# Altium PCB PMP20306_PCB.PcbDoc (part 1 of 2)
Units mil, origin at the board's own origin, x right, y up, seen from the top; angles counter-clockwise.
Board outline 1000 x 1500 mil, 4 copper layers (Top Layer, Signal Layer 1, Signal Layer 2, Bottom Layer), stack 42.6 mil thick; 50 components, 30 nets, 132 pads, 42 vias.
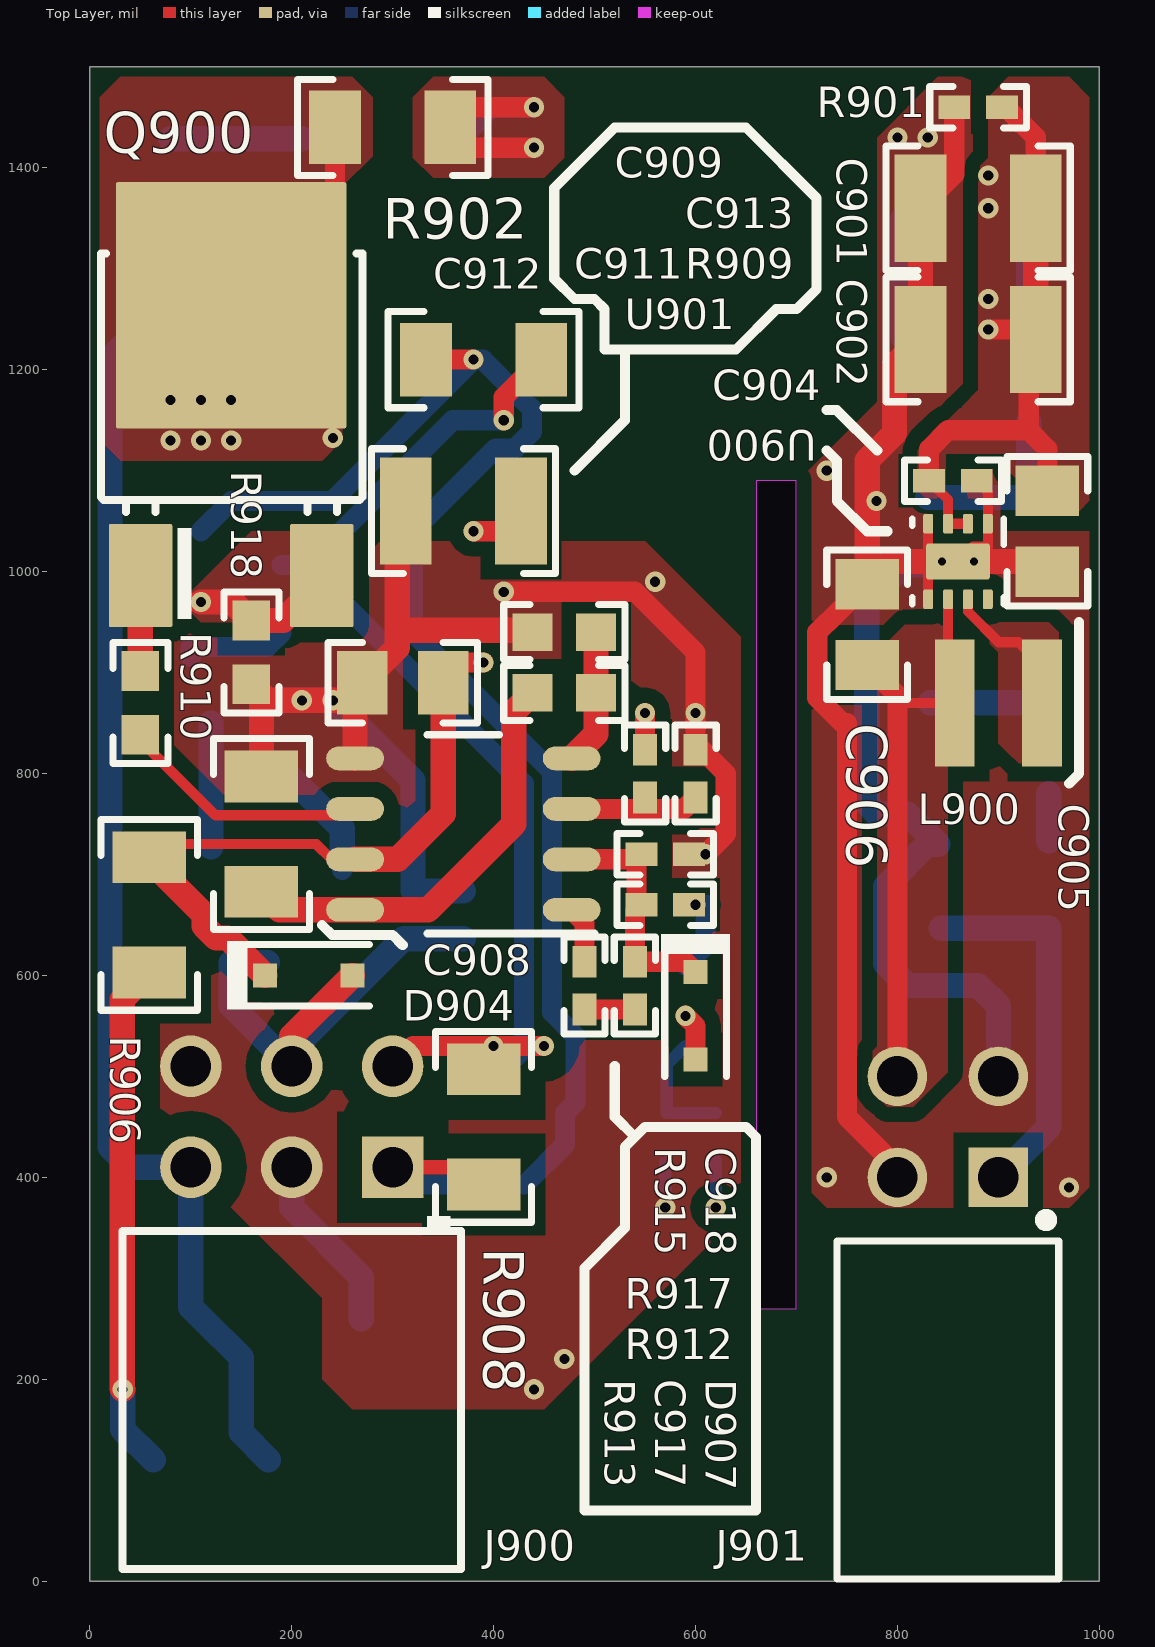
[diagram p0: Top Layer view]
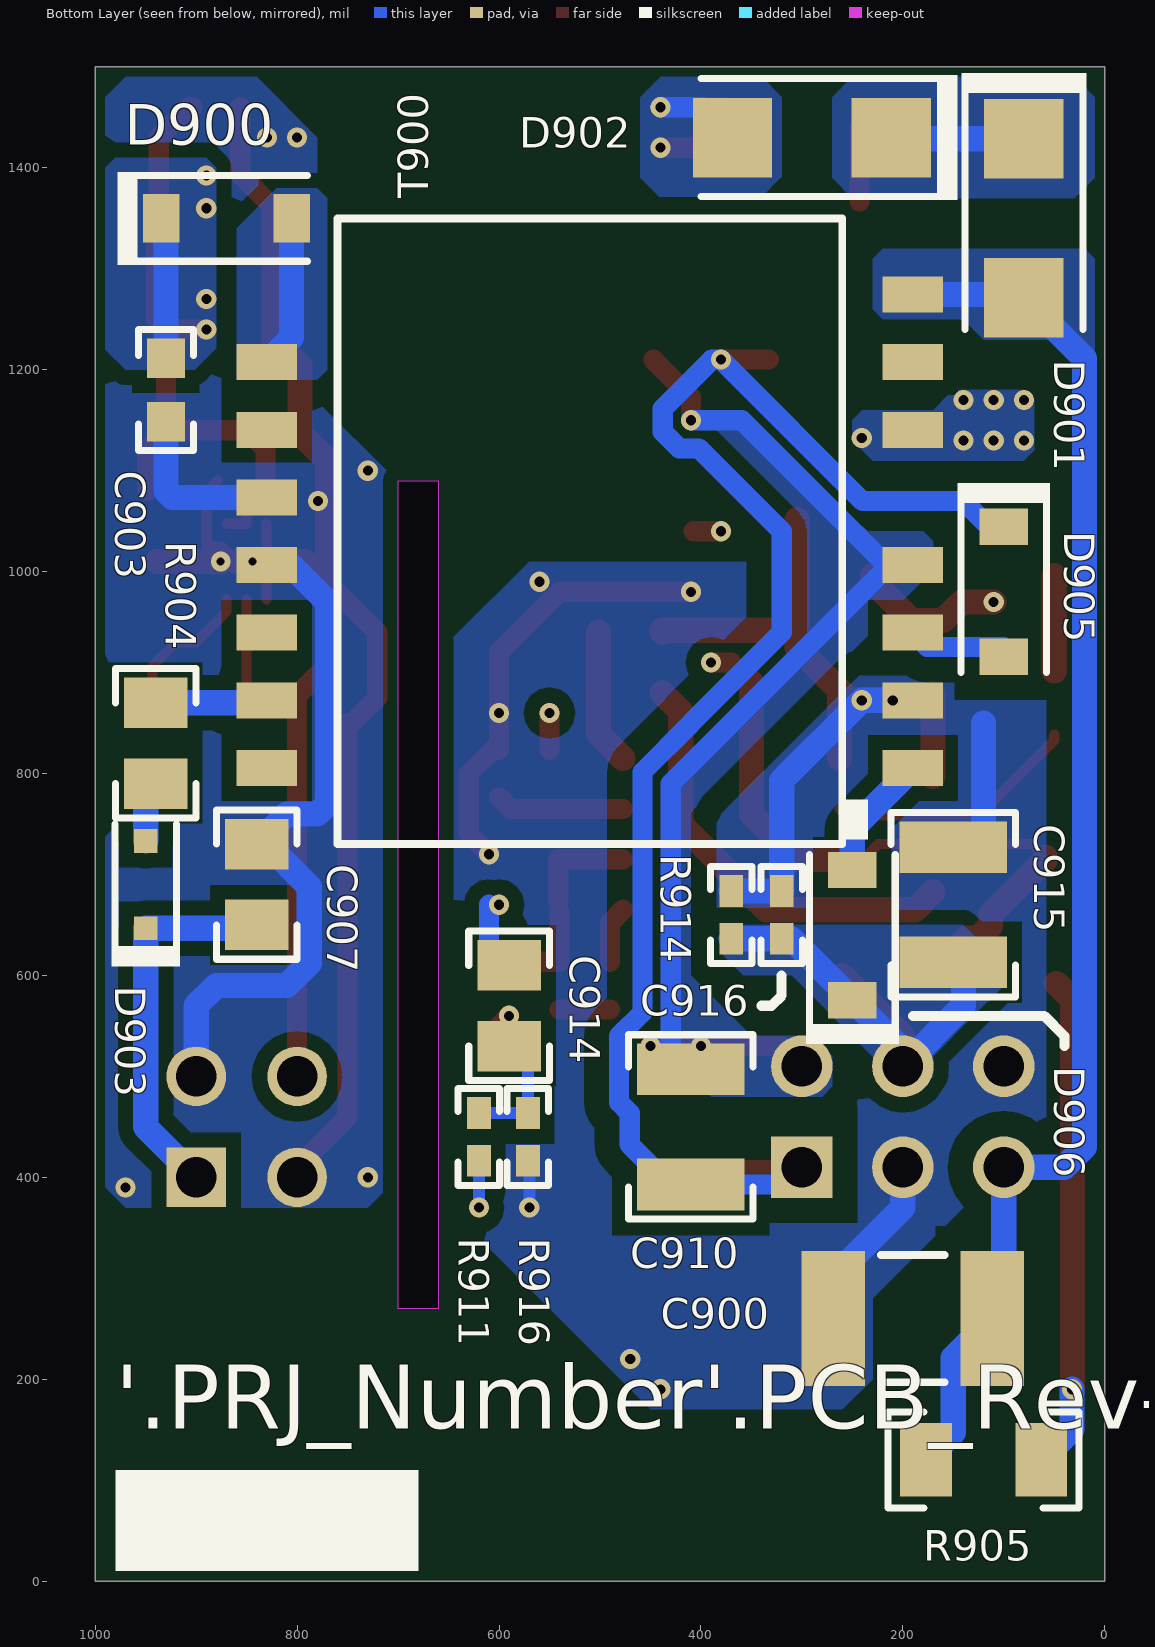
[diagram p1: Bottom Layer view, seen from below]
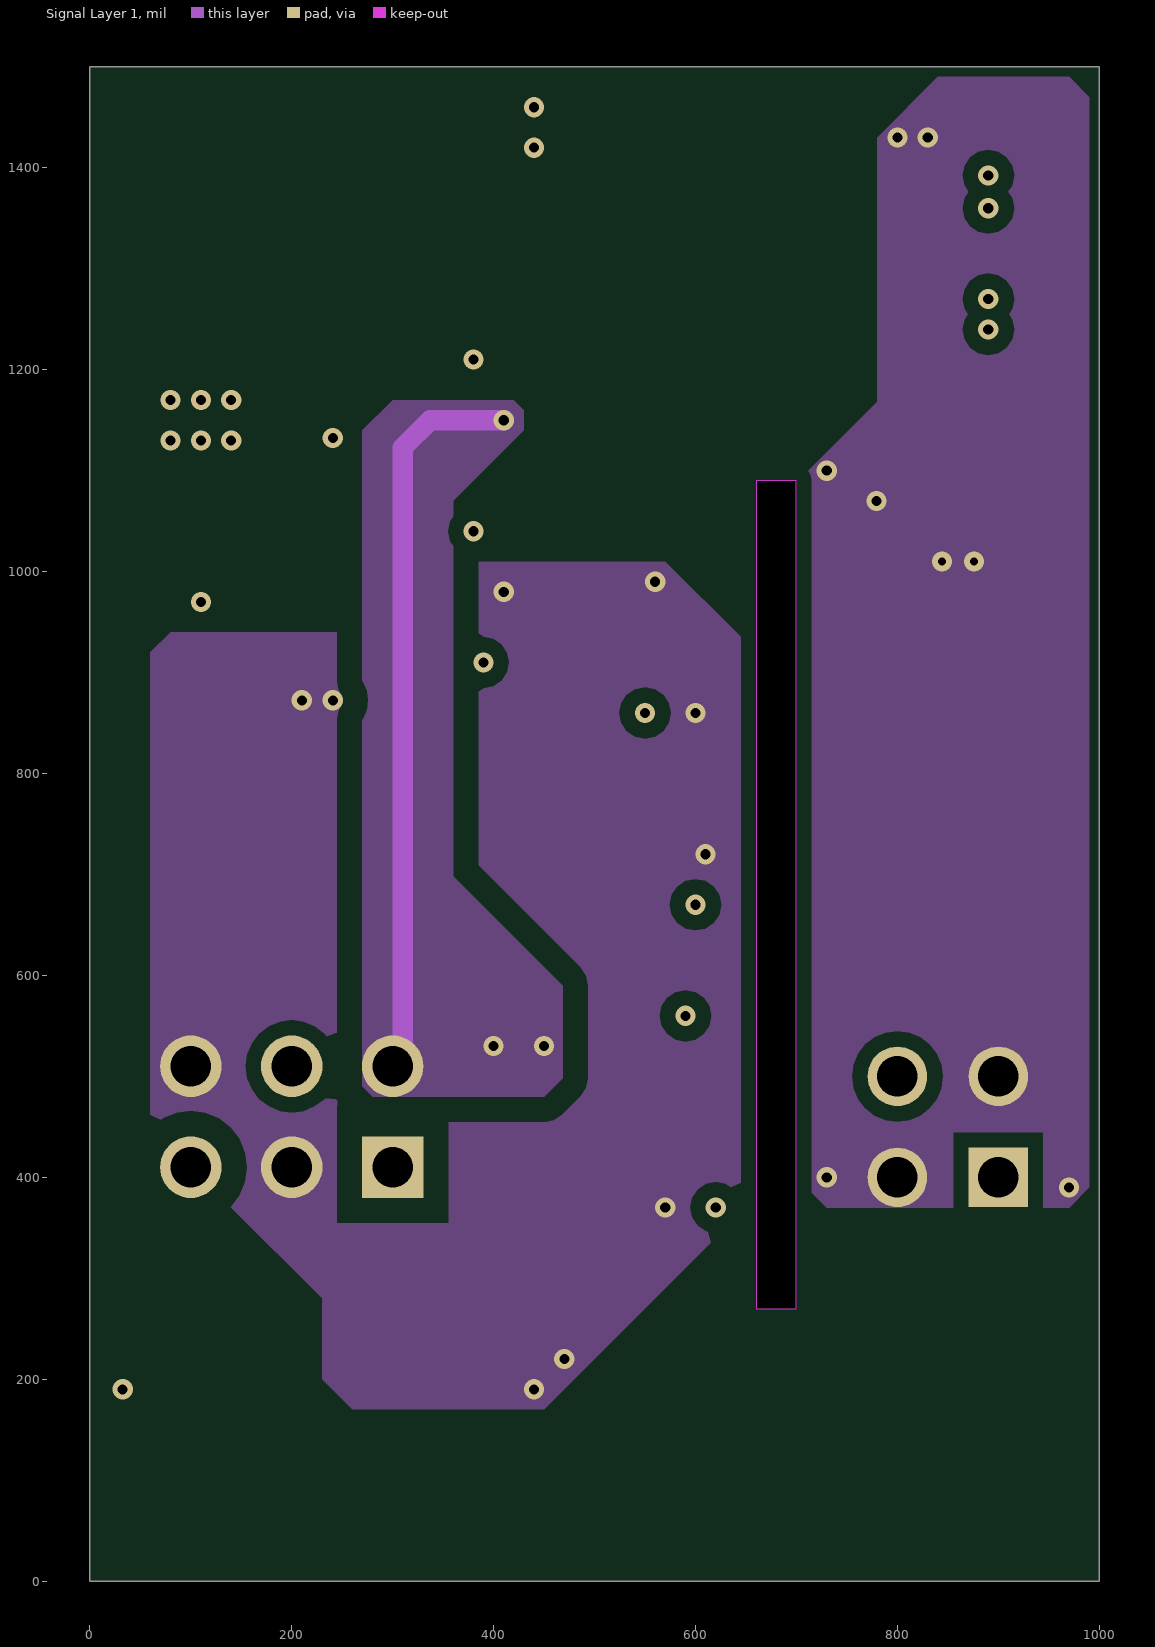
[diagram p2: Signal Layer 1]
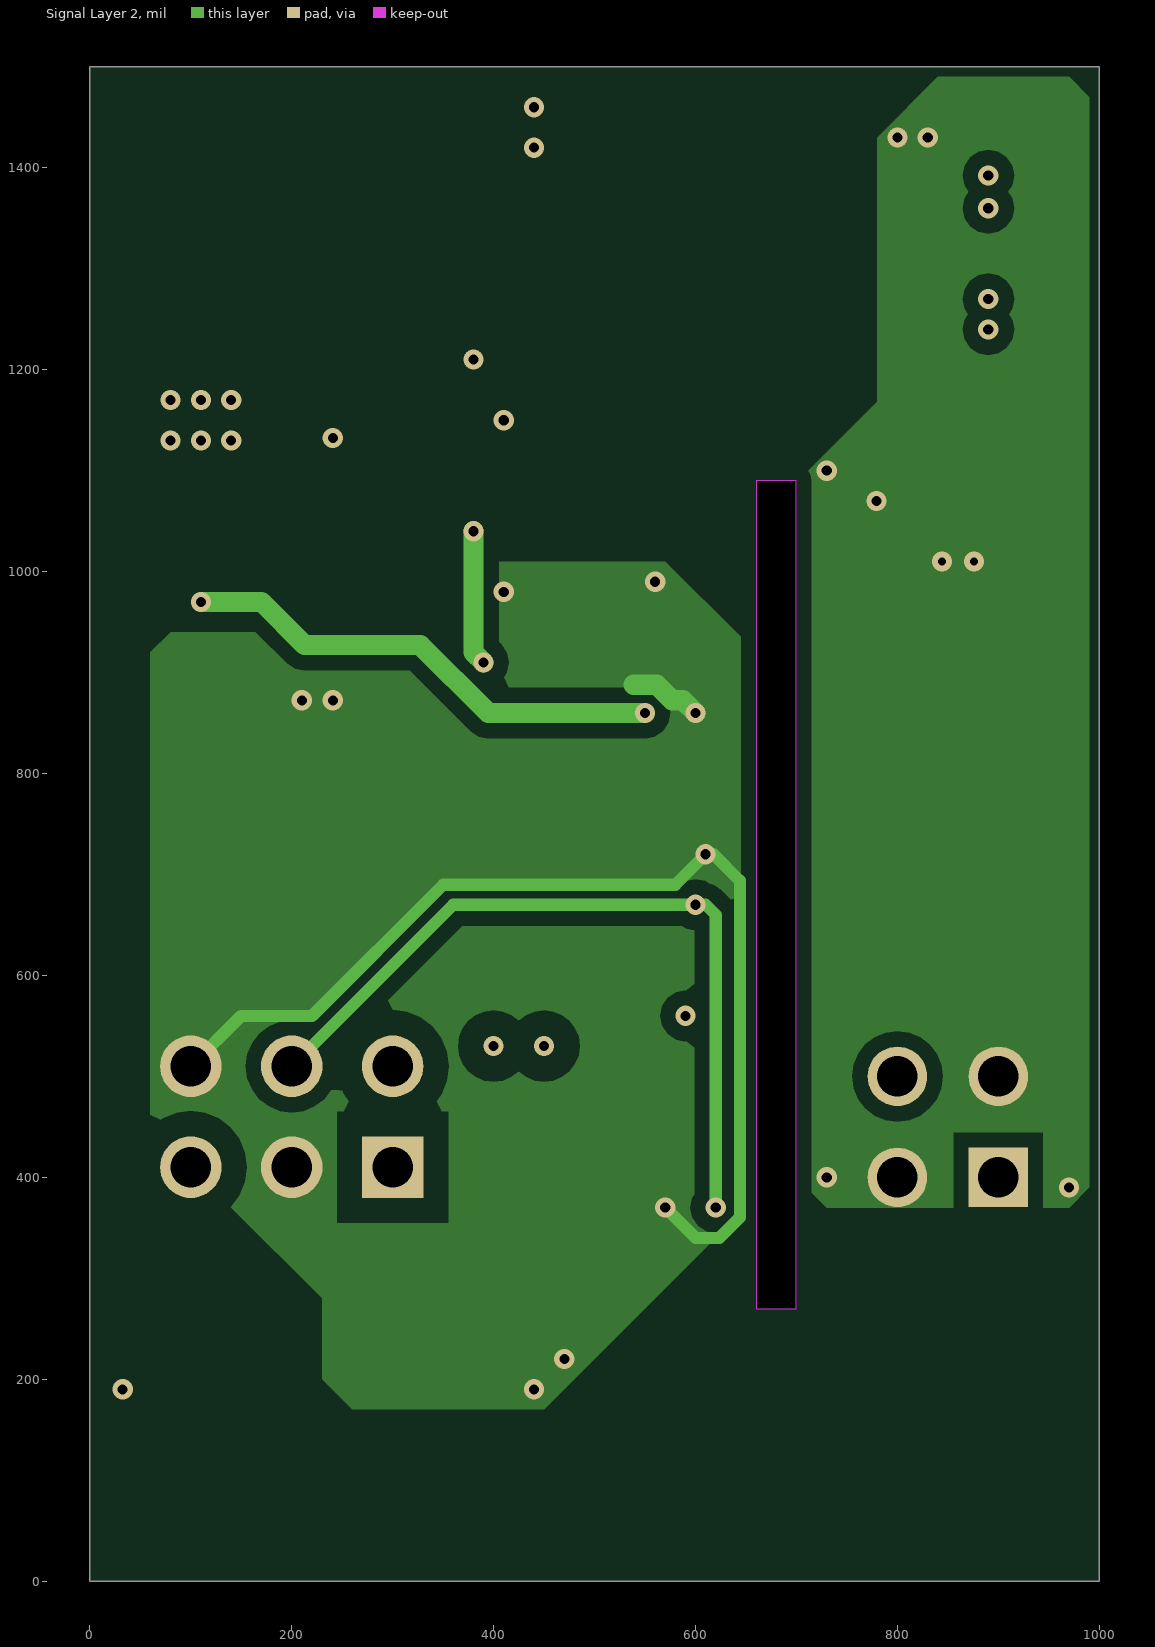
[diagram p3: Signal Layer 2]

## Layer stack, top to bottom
Top Solder: solder mask 0.4, Solder Resist, Dk 3.5
Top Layer: signal copper 1.4
Dielectric1: prepreg 8, Dk 4.2
Signal Layer 1: signal copper 1.4
Dielectric 3: core 21, FR-4, Dk 4.2
Signal Layer 2: signal copper 1.4
Dielectric 2: prepreg 8, Dk 4.2
Bottom Layer: signal copper 1.4
Bottom Solder: solder mask 0.4, Solder Resist, Dk 3.5

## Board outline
0,0 1000,0 1000,1500 0,1500
cut-out: 660,270 700,270 700,1090 660,1090

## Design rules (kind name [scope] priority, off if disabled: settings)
AcuteAngle [All] p1: minimum=4.50000000000000E+0001 checktracksonly=FALSE
AssemblyTestPointUsage [All] p1: valid=2
Clearance Clearance_1 [InNetClass('HV') vs InNet('GND_PRI')] p1: gap=25
Clearance Clearance_Keepouts [((IsTrack Or IsArc) And Not InPoly) And IsFree and IsKeepOut vs ((IsTrack Or IsArc) And Not InPoly) And IsFree and IsKeepOut] p2: gap=0
Clearance Clearance_BoardEdge_MountingHoles [OnCopper and InComponentClass('Mounting Holes') vs IsKeepOut] p3: gap=40
Clearance Clearance_BoardEdge_Poly [OnCopper and InPoly vs IsKeepOut] p4: gap=25
Clearance Clearance_BoardEdge [OnCopper and Not InComponentClass('Logo') and not InComponentClass('FiducialMark') and not InRegion(1000,500,4000,800) and Not IsKeepout vs IsKeepOut] p5: gap=75
Clearance Clearance_Poly [InPolygon] p6: gap=15
Clearance [All] p7: gap=7.87
ComponentClearance ComponentClearance_MountingHoles_FiducialMarks [InComponentClass('Mounting Holes') vs InComponentClass('FiducialMark')] p1: gap=20 collisioncheckmode=3 verticalgap=10 showdistances=FALSE
ComponentClearance ComponentClearance_Shunt [InComponentClass('Header') vs InComponentClass('Shunt')] p2: gap=0 collisioncheckmode=3 verticalgap=0 showdistances=FALSE
ComponentClearance ComponentClearance_Logo [InComponentClass('Logo')] p3: gap=5 collisioncheckmode=3 verticalgap=10 showdistances=FALSE
ComponentClearance ComponentClearance_ScrewToNut [(HasFootprint('NY PMS 440 0025 PH')) vs (HasFootprint('Keystone_1902C'))] p4: gap=20 collisioncheckmode=3 verticalgap=100000 showdistances=FALSE
ComponentClearance ComponentClearance_MountingHoles [InComponentClass('Mounting Holes')] p5: gap=20 collisioncheckmode=3 verticalgap=10 showdistances=FALSE
ComponentClearance ComponentClearance_SmallPassives [HasFootprint('0201*') or HasFootprint('0402*') or HasFootprint('0508') or HasFootprint('0603*') or HasFootprint('0612') or HasFootprint('0805*') or HasFootprint('0815*') or HasFootprint('0830*') or HasFootprint('1206*') or HasFootprint('1210*') or HasFootprint('1808*') or HasFootprint('1812*') or HasFootprint('1825*') or HasFootprint('2010*') or HasFootprint('2220*') or HasFootprint('2225*') or HasFootprint('2512*') or HasFootprint('2728*') or HasFootprint('3518*') vs HasFootprint('0201*') or HasFootprint('0402*') or HasFootprint('0508') or HasFootprint('0603*') or HasFootprint('0612') or HasFootprint('0805*') or HasFootprint('0815*') or HasFootprint('0830*') or HasFootprint('1206*') or HasFootprint('1210*') or HasFootprint('1808*') or HasFootprint('1812*') or HasFootprint('1825*') or HasFootprint('2010*') or HasFootprint('2220*') or HasFootprint('2225*') or HasFootprint('2512*') or HasFootprint('2728*') or HasFootprint('3518*')] p6: gap=20 collisioncheckmode=3 verticalgap=20 showdistances=FALSE
ComponentClearance ComponentClearance_THtoSMT [IsThruComponent vs IsSMTComponent] p7: gap=10 collisioncheckmode=3 verticalgap=10 showdistances=FALSE
ComponentClearance ComponentClearance_THtoTH [IsThruComponent vs IsThruComponent] p8: gap=10 collisioncheckmode=3 verticalgap=10 showdistances=FALSE
ComponentClearance [All] p9: gap=10 collisioncheckmode=3 verticalgap=10 showdistances=FALSE
DiffPairsRouting [All] p1: maxlimit=100 minlimit=10 mostfreqgap=10 toplayer_minwidth=15 toplayer_maxwidth=15 toplayer_prefwidth=15 midlayer1_minwidth=15 midlayer1_maxwidth=15 midlayer1_prefwidth=15 midlayer2_minwidth=15 midlayer2_maxwidth=15 midlayer2_prefwidth=15 bottomlayer_minwidth=15 bottomlayer_maxwidth=15 bottomlayer_prefwidth=15 maxuncoupledlength=1000
FabricationTestPointUsage TestPointUsage [All] p1: valid=2 allowmultiple=FALSE
FabricationTestpoint Testpoint [All] p1: side=3 testpointundercomponent=TRUE minsize=40 maxsize=100 preferedsize=60 minholesize=0 maxholesize=40 preferedholesize=32 testpointgrid=1 allowsidetop=TRUE allowsidebottom=TRUE usegrid=TRUE gridtolerance=0.01
FanoutControl Fanout_LCC [IsLCC] p1: bgadir=Out bgaviamode=Centered fanoutstyle=Auto fanoutdirection=Alternating viagrid=1 // Fanout_LCC (Default Rule)
FanoutControl Fanout_BGA [IsBGA] p2: bgadir=Out bgaviamode=Centered fanoutstyle=Auto fanoutdirection=Alternating viagrid=1 // Fanout_BGA (Default Rule)
FanoutControl Fanout_Default [All] p4: bgadir=Out bgaviamode=Centered fanoutstyle=Auto fanoutdirection=Alternating viagrid=1 // Fanout_Default (Default Rule)
FanoutControl Fanout_Small [(CompPinCount < 5)] p5: bgadir=Out bgaviamode=Centered fanoutstyle=Auto fanoutdirection=OutThenIn viagrid=1 // Fanout_Small (Default Rule)
Height [All] p1: minheight=0 maxheight=3000 prefheight=500
HoleSize [All] p1: absolutevalues=TRUE maxlimit=251 minlimit=7 maxpercent=80.000 minpercent=20.000
MinimumAnnularRing MinimumAnnularRing_ThermalPadVias [IsVia and InAnyComponent] p1: minimumring=5.91
MinimumAnnularRing [All] p2: minimumring=4.9
MinimumSolderMaskSliver MinimumSolderMaskSliver_Logo [InComponentClass('Logo') vs InComponentClass('Logo')] p1: minsoldermaskwidth=0.7
MinimumSolderMaskSliver [All] p2: minsoldermaskwidth=2
PlaneConnect [All] p1: planeconnectstyle=Relief reliefexpansion=10 reliefentries=4 reliefconductorwidth=10 reliefairgap=10
PolygonConnect PolygonConnect_13 [All vs IsNamedPolygon('Q900_4') Or  IsNamedPolygon('Q900_4') Or  IsNamedPolygon('5V') Or  IsNamedPolygon('L900_1') Or  IsNamedPolygon('D900_2') Or  IsNamedPolygon('D902_2') Or  IsNamedPolygon('GND_PRI') Or  IsNamedPolygon('SGND') Or  IsNamedPolygon('HSS') Or  IsNamedPolygon('HSS') Or  IsNamedPolygon('C901_2') Or  IsNamedPolygon('12VPL') Or  IsNamedPolygon('C901_2') Or  IsNamedPolygon('D901_1') Or  IsNamedPolygon('D902_2') Or  IsNamedPolygon('B+') Or  IsNamedPolygon('Q900_3')] p1: connectstyle=Direct reliefconductorwidth=10 reliefentries=4 polygonreliefangle="90 Angle" airgapwidth=10
PolygonConnect PolygonConnect_12 [All vs IsNamedPolygon('C901_2') Or  IsNamedPolygon('C901_2') Or  IsNamedPolygon('GND_PRI') Or  IsNamedPolygon('5V') Or  IsNamedPolygon('B+') Or  IsNamedPolygon('D900_2') Or  IsNamedPolygon('12VPL') Or  IsNamedPolygon('D902_2') Or  IsNamedPolygon('Q900_3') Or  IsNamedPolygon('Q900_4') Or  IsNamedPolygon('D901_1') Or  IsNamedPolygon('SGND') Or  IsNamedPolygon('D902_2') Or  IsNamedPolygon('L900_1') Or  IsNamedPolygon('Q900_4')] p2: connectstyle=Direct reliefconductorwidth=10 reliefentries=4 polygonreliefangle="90 Angle" airgapwidth=10
PolygonConnect PolygonConnect_11 [All vs IsNamedPolygon('B+') Or  IsNamedPolygon('Q900_3') Or  IsNamedPolygon('12VPL') Or  IsNamedPolygon('D902_2') Or  IsNamedPolygon('D901_1') Or  IsNamedPolygon('5V') Or  IsNamedPolygon('D902_2') Or  IsNamedPolygon('Q900_4') Or  IsNamedPolygon('L900_1') Or  IsNamedPolygon('C901_2') Or  IsNamedPolygon('C901_2') Or  IsNamedPolygon('D900_2') Or  IsNamedPolygon('SGND') Or  IsNamedPolygon('Q900_4')] p3: connectstyle=Direct reliefconductorwidth=10 reliefentries=4 polygonreliefangle="90 Angle" airgapwidth=10
PolygonConnect PolygonConnect_10 [All vs IsNamedPolygon('Q900_4') Or  IsNamedPolygon('D902_2') Or  IsNamedPolygon('B+') Or  IsNamedPolygon('D901_1') Or  IsNamedPolygon('D902_2') Or  IsNamedPolygon('Q900_3')] p4: connectstyle=Direct reliefconductorwidth=10 reliefentries=4 polygonreliefangle="90 Angle" airgapwidth=10
PolygonConnect PolygonConnect_9 [All vs IsNamedPolygon('C11_1') Or  IsNamedPolygon('Vin') Or  IsNamedPolygon('Vin') Or  IsNamedPolygon('5V') Or  IsNamedPolygon('D6_2') Or  IsNamedPolygon('Q3_3') Or  IsNamedPolygon('GND2') Or  IsNamedPolygon('GND2') Or  IsNamedPolygon('GND') Or  IsNamedPolygon('Q3_4') Or  IsNamedPolygon('12V5') Or  IsNamedPolygon('GND') Or  IsNamedPolygon('12V5') Or  IsNamedPolygon('D3_1')] p5: connectstyle=Direct reliefconductorwidth=10 reliefentries=4 polygonreliefangle="90 Angle" airgapwidth=10
PolygonConnect PolygonConnect_8 [All vs IsNamedPolygon('C11_1') Or  IsNamedPolygon('Vin') Or  IsNamedPolygon('12V5') Or  IsNamedPolygon('Q3_3') Or  IsNamedPolygon('GND2') Or  IsNamedPolygon('GND2') Or  IsNamedPolygon('5V') Or  IsNamedPolygon('Q3_4') Or  IsNamedPolygon('12V5')] p6: connectstyle=Direct reliefconductorwidth=10 reliefentries=4 polygonreliefangle="90 Angle" airgapwidth=10
PolygonConnect PolygonConnect_7 [All vs IsNamedPolygon('GND2') Or  IsNamedPolygon('GND2') Or  IsNamedPolygon('5V') Or  IsNamedPolygon('12V5') Or  IsNamedPolygon('12V5') Or  IsNamedPolygon('C11_1')] p7: connectstyle=Direct reliefconductorwidth=10 reliefentries=4 polygonreliefangle="90 Angle" airgapwidth=10
PolygonConnect PolygonConnect_6 [All vs IsNamedPolygon('GND2') Or  IsNamedPolygon('SGND') Or  IsNamedPolygon('GND1') Or  IsNamedPolygon('C901_1') Or  IsNamedPolygon('SGND') Or  IsNamedPolygon('GND2') Or  IsNamedPolygon('GND1')] p8: connectstyle=Direct reliefconductorwidth=10 reliefentries=4 polygonreliefangle="90 Angle" airgapwidth=10
PolygonConnect PolygonConnect_5 [All vs IsNamedPolygon('GND1') Or  IsNamedPolygon('GND1')] p9: connectstyle=Direct reliefconductorwidth=10 reliefentries=4 polygonreliefangle="90 Angle" airgapwidth=10
PolygonConnect PolygonConnect_4 [All vs IsNamedPolygon('C21_1') Or  IsNamedPolygon('C5_1') Or  IsNamedPolygon('C12_2') Or  IsNamedPolygon('C2_2') Or  IsNamedPolygon('C13_1') Or  IsNamedPolygon('C28_1') Or  IsNamedPolygon('C6_1') Or  IsNamedPolygon('GND') Or  IsNamedPolygon('GND2') Or  IsNamedPolygon('C14_1') Or  IsNamedPolygon('C13_1') Or  IsNamedPolygon('Q1_3') Or  IsNamedPolygon('C14_1') Or  IsNamedPolygon('C5_1') Or  IsNamedPolygon('GND2') Or  IsNamedPolygon('C28_1') Or  IsNamedPolygon('D5_2') Or  IsNamedPolygon('D6_2') Or  IsNamedPolygon('D2_1') Or  IsNamedPolygon('C12_2') Or  IsNamedPolygon('D2_1') Or  IsNamedPolygon('C4_1') Or  IsNamedPolygon('C4_1') Or  IsNamedPolygon('C2_2') Or  IsNamedPolygon('GND') Or  IsNamedPolygon('C33_1') Or  IsNamedPolygon('C9_1')] p10: connectstyle=Direct reliefconductorwidth=10 reliefentries=4 polygonreliefangle="90 Angle" airgapwidth=10
PolygonConnect PolygonConnect_3 [All vs IsNamedPolygon('C28_1') Or  IsNamedPolygon('C12_2') Or  IsNamedPolygon('C28_1') Or  IsNamedPolygon('C9_1') Or  IsNamedPolygon('D5_2') Or  IsNamedPolygon('C12_2') Or  IsNamedPolygon('C2_2') Or  IsNamedPolygon('C14_1') Or  IsNamedPolygon('C4_1') Or  IsNamedPolygon('C14_1') Or  IsNamedPolygon('D6_2') Or  IsNamedPolygon('GND2') Or  IsNamedPolygon('Q1_3') Or  IsNamedPolygon('C5_1') Or  IsNamedPolygon('D2_1') Or  IsNamedPolygon('C4_1') Or  IsNamedPolygon('C13_1') Or  IsNamedPolygon('C5_1') Or  IsNamedPolygon('C13_1') Or  IsNamedPolygon('C33_1') Or  IsNamedPolygon('D2_1') Or  IsNamedPolygon('GND') Or  IsNamedPolygon('GND') Or  IsNamedPolygon('GND2') Or  IsNamedPolygon('C2_2') Or  IsNamedPolygon('C6_1') Or  IsNamedPolygon('C21_1')] p11: connectstyle=Direct reliefconductorwidth=10 reliefentries=4 polygonreliefangle="90 Angle" airgapwidth=10
PolygonConnect PolygonConnect_2 [All vs IsNamedPolygon('C21_1') Or  IsNamedPolygon('C4_1') Or  IsNamedPolygon('D5_2') Or  IsNamedPolygon('C5_1') Or  IsNamedPolygon('C14_1') Or  IsNamedPolygon('C13_1') Or  IsNamedPolygon('C4_1') Or  IsNamedPolygon('C33_1') Or  IsNamedPolygon('C12_2') Or  IsNamedPolygon('D2_1') Or  IsNamedPolygon('C2_2') Or  IsNamedPolygon('C28_1') Or  IsNamedPolygon('C12_2') Or  IsNamedPolygon('D2_1') Or  IsNamedPolygon('C5_1') Or  IsNamedPolygon('Q1_3') Or  IsNamedPolygon('GND') Or  IsNamedPolygon('D6_2') Or  IsNamedPolygon('C6_1') Or  IsNamedPolygon('C2_2') Or  IsNamedPolygon('C14_1') Or  IsNamedPolygon('C28_1') Or  IsNamedPolygon('C13_1') Or  IsNamedPolygon('C9_1') Or  IsNamedPolygon('GND')] p12: connectstyle=Direct reliefconductorwidth=10 reliefentries=4 polygonreliefangle="90 Angle" airgapwidth=10
PolygonConnect PolygonConnect_1 [All vs IsNamedPolygon('C28_1') Or  IsNamedPolygon('D5_2') Or  IsNamedPolygon('C5_1') Or  IsNamedPolygon('C5_1') Or  IsNamedPolygon('D2_1') Or  IsNamedPolygon('C21_1') Or  IsNamedPolygon('C9_1') Or  IsNamedPolygon('C4_1') Or  IsNamedPolygon('C14_1') Or  IsNamedPolygon('C28_1') Or  IsNamedPolygon('C6_1') Or  IsNamedPolygon('C12_2') Or  IsNamedPolygon('C33_1') Or  IsNamedPolygon('C4_1') Or  IsNamedPolygon('C13_1') Or  IsNamedPolygon('C12_2') Or  IsNamedPolygon('D6_2') Or  IsNamedPolygon('C2_2') Or  IsNamedPolygon('C14_1') Or  IsNamedPolygon('D2_1') Or  IsNamedPolygon('C2_2') Or  IsNamedPolygon('C13_1')] p13: connectstyle=Direct reliefconductorwidth=10 reliefentries=4 polygonreliefangle="90 Angle" airgapwidth=10
PolygonConnect [All] p14: connectstyle=Relief reliefconductorwidth=10 reliefentries=4 polygonreliefangle="90 Angle" airgapwidth=10
RoutingVias ThermalPadVias [IsVia and InAnyComponent] p1: holewidth=7.87 width=19.68 viastyle="Through Hole" minholewidth=7.87 minwidth=19.68 maxholewidth=12.99 maxwidth=23.62
RoutingVias [All] p2: holewidth=16 width=34 viastyle="Through Hole" minholewidth=7.87 minwidth=20 maxholewidth=40 maxwidth=65
SilkToBoardRegionClearance [Not ((IsComment or IsDesignator) And (Hide <> 'False')) and not InRegion(1000,500,4000,800)] p1:
SilkToSilkClearance SilkToSilkClearance_Pb-FreeLogo [(HasFootprint('Pb-Free_Overlay_Medium') OR HasFootprint('Pb-Free_Overlay_Small')) vs (HasFootprint('Pb-Free_Overlay_Medium') OR HasFootprint('Pb-Free_Overlay_Small'))] p1: silktosilkclearance=0
SilkToSilkClearance [All] p2: silktosilkclearance=1
SilkToSolderMaskClearance "Silk to Solder Mask Opening" [All] p1: minsilkscreentomaskgap=1 clearancetoexposedcopper=FALSE
SolderMaskExpansion [All] p1: expansion=1.97
Width [All] p1: maxlimit=100 minlimit=6 preferedwidth=10 checkconnectedcopper=TRUE
14 further rules are at their usual default settings.

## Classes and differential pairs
component class NoTherm: C900
net class HV: 12VPH B+ HSS NetD901_1 NetD902_2 NetD905_2 NetQ900_4 NetR905_2

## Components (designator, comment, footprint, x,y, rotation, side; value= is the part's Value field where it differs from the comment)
C900 "GRM43DR72J104KW01L" 1812 190,260 r0 bottom
C901 "GRM32ER61A476KE20L" 1210_270 880,1360 r0 top
C902 "GRM32ER61A476KE20L" 1210_270 880,1230 r0 top
C903 "06033C104JAT2A" 0603 930,1180 r270 bottom
C904 "885012205037" 0402 855,1090 r0 top
C905 "885012207026" 0805_HV 948.54,1040 r270 top
C906 "JMK212BJ226MG-T" 0805_HV 770,947.5 r90 top
C907 "08055C104MAT2A" 0805_HV 840,690 r270 bottom
C908 "C1206C105K3RACTU" 1206 170,740 r90 top
C909 "GRM32ER61C476KE15L" 1210_270 370,1060 r0 top
C910 "GRM32ER61C476KE15L" 1210_270 410,450 r270 bottom
C911 "CL21B105KBFNNNE" 0805_HV 310,890 r180 top
C912 "12063D225KAT2A" 1206 390,1210 r0 top
C913 "06031C221KAT2A" 0603 470,940 r0 top
C914 "0805ZD475KAT2A" 0805_HV 590,570 r270 bottom
C915 "GRM32ER61C476KE15L" 1210_270 150,670 r270 bottom
C916 "885012205037" 0402 320,660 r90 bottom
C917 "GRM155R61C223KA01D" 0402 540,590 r90 top
C918 "GRM1555C1H681JA01D" 0402 600,800 r90 top
D900 "RB168MM150TR" SOD-123 870,1350 r180 bottom
D901 "SMAJ130A" SMA 80,1350 r270 bottom
D902 "US1M-13-F" SMA 290,1430 r0 bottom
D903 "MMDL914-TP" sod-323 950,690 r90 bottom
D904 "BAS20HT1G" sod-323 216.93,600 r0 top
D905 "RB168MM150TR" SOD-123 100,980 r270 bottom
D906 "RB168MM150TR" SOD-123 250,640 r90 bottom
D907 "MMDL914-TP" sod-323 600,560 r270 top
J900 "PPPC032LJBN-RC" Sullins_xPxC032LJBN 200,460 r180 top
J901 "PPPC022LJBN-RC" Sullins_PPPC022LJBN-RC 900,400 r180 top
L900 "744025002" WE-TPC_2828 900,870 r180 top
Q900 "IPD80R1K0CEBTMA1" DPAK 140,1130 r90 top
R901 "CRCW04024K99FKED" 0402 880,1460 r0 top
R902 "CRCW120651R0JNEA" 1206 300,1440 r180 top
R904 "CRCW08054R99FKEA" 0805_HV 940,830 r90 bottom
R905 "CRCW1206330KJNEA" 1206 120,120 r180 bottom
R906 "CRCW1206330KJNEA" 1206 58.8,660 r90 top
R908 "CRCW12062K00JNEA" 1206 390,450 r270 top
R909 "ERJ-3EKF3002V" 0603 470,880 r180 top
R910 "CRCW06030000Z0EA" 0603 50,870 r90 top
R911 "CRCW04021M00JNED" 0402 620,440 r270 bottom
R912 "CRCW04029K53FKED" 0402 570,670 r0 top
R913 "CRCW0402200KFKED" 0402 490,590 r90 top
R914 "CRCW04027K50JNED" 0402 370,660 r270 bottom
R915 "CRCW0402499RFKED" 0402 550,800 r90 top
R916 "CRCW040210K0FKED" 0402 571.46,440 r90 bottom
R917 "CRCW04022K49FKED" 0402 570,720 r180 top
R918 "CRCW060310R0FKEA" 0603 160,920 r90 top
T900 "RLTI-1184" Renco_RLTI-1184 510,1040 r0 bottom
U900 "TPS62163DSGR" DSG0008A 860,1010 r270 top
U901 "UCC3813D-4" D0008A_N 370,740 r180 top

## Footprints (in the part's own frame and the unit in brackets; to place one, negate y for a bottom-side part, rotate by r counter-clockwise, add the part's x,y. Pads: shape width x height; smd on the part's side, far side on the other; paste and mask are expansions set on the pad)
0402 [mm] "0402 from SM-752 data"
  rect 0.8x0.6 smd: 1(-0.6,0) 2(0.6,0)
  silkscreen extent -1.22,-0.52 1.22,0.52, body extent -0.55,-0.3 0.55,0.3, height 0.6
0603 [mm] "0603 from SM-752 data"
  rect 1x0.95 smd: 1(-0.8,0) 2(0.8,0)
  silkscreen extent -1.52,-0.69 1.52,0.69, body extent -0.87,-0.47 0.87,0.47, height 1
0805_HV [mil] "0805 with 30mil clearance between pads"
  rect 50x63 smd: 1(-40,0) 2(40,0)
  silkscreen extent -74,-40 74,40, body extent -43,-29 43,29, height 57
1206 [mm] "1206 from SM-752 data"
  rect 1.3x1.85 smd: 1(-1.45,0) 2(1.45,0)
  silkscreen extent -2.4,-1.21 2.4,1.21, body extent -1.7,-0.9 1.7,0.9, height 1.35
1210_270 [mm] "1210"
  rect 1.3x2.7 smd: 1(-1.45,0) 2(1.45,0)
  silkscreen extent -2.32,-1.57 2.32,1.57, body extent -1.7,-1.35 1.7,1.35, height 2.7
1812 [mm]
  rect 1.6x3.4 smd: 1(-2,0) 2(2,0)
  silkscreen extent -0.8,-1.6 0.8,1.6, body extent -2.4,-1.7 2.4,1.7, height 1.35
D0008A_N [mm] "SOIC, 8-Leads, Body 4.9x3.9mm, Pitch 1.27mm, IPC Medium Density"
  oval 1.45x0.6 smd: 1(-2.725,1.905) 2(-2.725,0.635) 3(-2.725,-0.635) 4(-2.725,-1.905) 5(2.725,-1.905) 6(2.725,-0.635) 7(2.725,0.635) 8(2.725,1.905)
  silkscreen extent -3.3,-2.5 0.9,2.5, body extent -3,-2.45 3,2.45, height 1.63
DPAK [mm] "D-PAK, 3-Pads, Body 6.22x6.73mm (max), TO-252AA using nominal STEP model"
  rrect6% 2.6x1.6 smd: 1(-3.4,2.28) 3(-3.4,-2.28)
  rrect2% 6.2x5.8 smd paste-2.9: 4(3.4,0)
  silkscreen extent -4.5,-3.3 4.7,3.28, body extent -3.86,-3.29 5.84,3.29, height 2.48
DSG0008A [mm] "SON, 8-Leads, Body 2x2mm, Pitch 0.5mm, Thermal Pad 1.6x0.9mm, TI Recommended"
  rrect40% 0.5x0.25 smd: 1(-0.95,0.75) 2(-0.95,0.25) 3(-0.95,-0.25) 4(-0.95,-0.75) 5(0.95,-0.75) 6(0.95,-0.25) 7(0.95,0.25) 8(0.95,0.75)
  rrect11% 0.9x1.6 smd paste-0.45: 9(0,0)
  silkscreen extent -1.07,-1.15 1.07,1.15, body extent -1.05,-1.05 1.05,1.05, height 0.8
Renco_RLTI-1184 [mil] "SMT, 16-Leads, Body 680x620mil, Pitch 67mil"
  rect 60x35.69 smd: 1(-320,234.5) 2(-320,167.5) 3(-320,100.5) 4(-320,33.5) 6(-320,-100.5) 7(-320,-167.5) 8(-320,-234.5) 10(320,-167.5) 11(320,-100.5) 12(320,-33.5) 13(320,33.5) 14(320,100.5) 15(320,167.5) 16(320,234.5)
  silkscreen extent -276,-310 250,310, body extent -340,-310 340,310, height 520
SMA [mm] "Molded Diode, 2-Leads, Body 4.3x2.6mm, IPC Medium Density, based on OnSemi component dimensions and land pattern"
  rect 2x2 smd: 1(-2,0) 2(2,0)
  silkscreen extent -3.66,-1.57 2.79,1.57, body extent -2.6,-1.3 2.6,1.3, height 2.42
SOD-123 [mm] "On Semi recommended land pattern"
  rect 0.915x1.22 smd: 1(-1.637,0) 2(1.637,0)
  silkscreen extent -2.74,-1.17 2.03,1.17, body extent -1.93,-0.9 1.93,0.9, height 1.35
sod-323 [mm] "NXP recommended land pattern"
  rect 0.6x0.6 smd paste-0.05: 1(-1.1,0) 2(1.1,0)
  silkscreen extent -2.06,-0.86 1.53,0.86, body extent -1.3,-0.67 1.3,0.68, height 1.1
Sullins_PPPC022LJBN-RC [mm] "Sullins Right Angle Header"
  rect 1.5x1.5 hole 1.02 paste+0: 1(0,0)
  round 1.5 hole 1.02 paste+0: 2(0,-2.54) 3(2.54,0) 4(2.54,-2.54)
  silkscreen extent -1.52,0.94 4.06,10.11, body extent -1.52,-2.85 4.06,10.03, height 5.2
Sullins_xPxC032LJBN [mm] "Receptacle, 2.54mm, 3x2, R/A, TH"
  rect 1.55x1.55 hole 1.02: 1(-2.54,1.27)
  round 1.55 hole 1.02: 2(-2.54,-1.27) 3(0,1.27) 4(0,-1.27) 5(2.54,1.27) 6(2.54,-1.27)
  silkscreen extent -4.25,2.5 4.25,11.38, body extent -4.25,-1.57 4.25,11.38, height 8.13
WE-TPC_2828 [mm] "WURTH"
  rect 1x3.2 smd: 1(-1.1,0) 2(1.1,0)
  body extent -1.5,-1.5 1.5,1.5, height 3

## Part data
C900: "CAP, CERM, 0.1uF, 630V, +/-10%, X7R, 1812"
C901 C902: "CAP, CERM, 47 µF, 10 V, +/- 10%, X5R, 1210"
C903: "CAP, CERM, 0.1uF, 25V, +/-5%, X7R, 0603"
C904 C916: "CAP, CERM, 0.1 µF, 16 V, +/- 10%, X7R, 0402"
C905: "CAP, CERM, 10 µF, 10 V, +/- 10%, X7R, 0805"
C906: "CAP, CERM, 22 µF, 6.3 V, +/- 20%, X5R, 0805"
C907: "CAP, CERM, 0.1uF, 50V, +/-20%, X7R, 0805"
C908: "CAP, CERM, 1 µF, 25 V, +/- 10%, X7R, 1206"
C909 C910 C915: "CAP, CERM, 47 µF, 16 V, +/- 10%, X5R, 1210"
C911: "CAP, CERM, 1 µF, 50 V, +/- 10%, X7R, 0805"
C912: "CAP, CERM, 2.2 µF, 25 V, +/- 10%, X5R, 1206"
C913: "CAP, CERM, 220pF, 100V, +/-10%, X7R, 0603"
C914: "CAP, CERM, 4.7uF, 10V, +/-10%, X5R, 0805"
C917: "CAP, CERM, 0.022 µF, 16 V, +/- 10%, X5R, 0402"
C918: "CAP, CERM, 680 pF, 50 V, +/- 5%, C0G/NP0, 0402"
D900 D905 D906: library part RB160M-60TR, "DIODE SCHOTTKY 150V 1A PMDU"
D901: library part SMAJ120A, "DIODE TVS 130V 400W UNI 5% SMD"
D902: "Diode, Ultrafast, 1000V, 1A, SMA"
D903: "Diode, Switching, 100 V, 0.2 A, SOD-323"
D904: library part BAS316,115, "DIODE SWITCH 200V 200MA SOD323"
D907: "Diode, Switching, 100V, 0.2A, SOD-323"
J900: "Receptacle, 2.54mm, 3x2, Gold, R/A, TH"
J901: "CONN FEMALE 4POS DL .1\" R/A GOLD"
L900: "Inductor, Shielded Drum Core, Ferrite, 2.2 µH, 1.8 A, 0.057 ohm, SMD"
Q900: "MOSFET, N-CH, 800 V, 5.7 A, DPAK"
R901: "RES, 4.99 k, 1%, 0.063 W, 0402"
R902: "RES, 51, 5%, 0.25 W, 1206"
R904: "RES, 4.99, 1%, 0.125 W, 0805"
R905 R906: "RES, 330 k, 5%, 0.25 W, 1206"
R908: "RES, 2.0 k, 5%, 0.25 W, 1206"
R909: "RES, 30.0 k, 1%, 0.1 W, AEC-Q200 Grade 0, 0603"
R910: "RES, 0, 5%, 0.1 W, 0603"
R911: "RES, 1.0 M, 5%, 0.063 W, 0402"
R912: "RES, 9.53 k, 1%, 0.063 W, 0402"
R913: "RES, 200 k, 1%, 0.063 W, 0402"
R914: "RES, 7.5 k, 5%, 0.063 W, 0402"
R915: "RES, 499, 1%, 0.063 W, 0402"
R916: "RES, 10.0 k, 1%, 0.063 W, 0402"
R917: "RES, 2.49 k, 1%, 0.063 W, 0402"
R918: "RES, 10.0, 1%, 0.1 W, 0603"
T900: "Transformer, 2300 uH, SMT"
U900: "Buck Step Down Regulator with 3 to 17 V Input and 5 V Output, -40 to 85 degC, 8-Pin WSON (DSG), Green (RoHS & no Sb/Br)"
U901: library part UCC28C42DR, "IC REG CTRLR PWM CM 8SOIC"

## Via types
v1: diameter 20, hole 10, Top Layer to Bottom Layer, 40 vias
v2: diameter 19.68, hole 7.87, Top Layer to Bottom Layer, 2 vias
